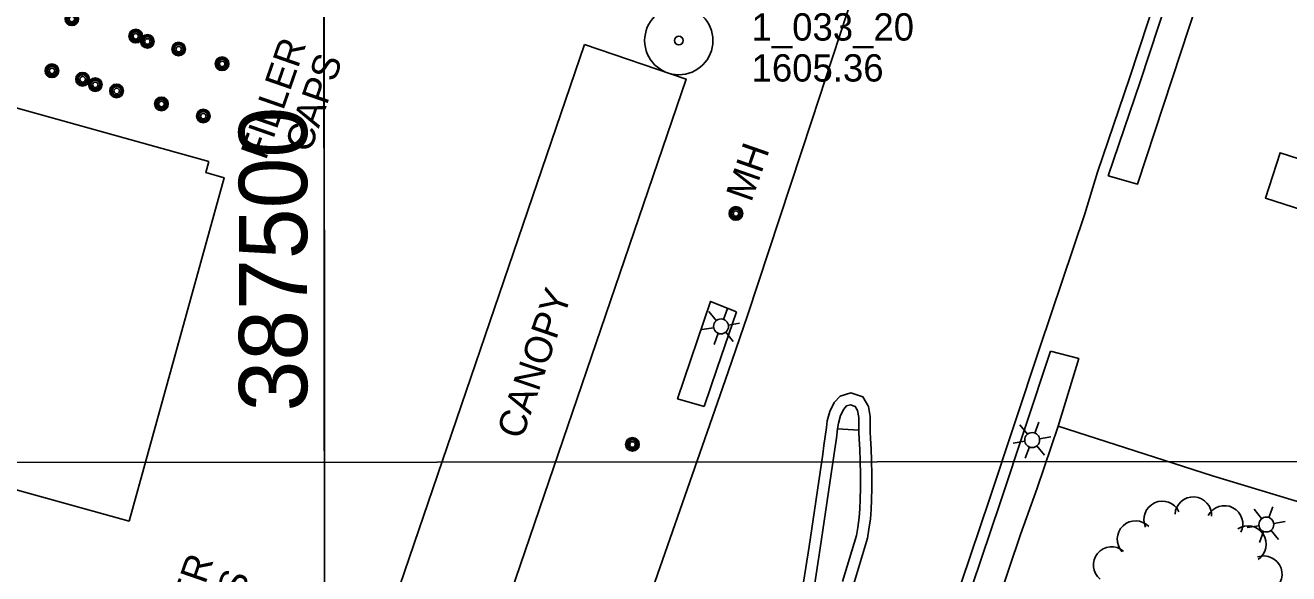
# Model space of a CAD drawing. Extents: x 189384 to 193282, y 256970 to 260388.
# Drawn here: x 190581.3 to 190859, y 258486.9 to 258607.4 of the extents above; entities that cross this region are included whole.
import ezdxf

# ---------------------------------------------------------------- set-up
doc = ezdxf.new("R2010")
doc.units = 0
for name, color, linetype in [('E_BLD_Name', 7, 'Continuous'), ('E_DRN_Grate', 7, 'Continuous'), ('E_DWY', 7, 'Continuous'), ('E_LAND_Vegetation', 7, 'Continuous'), ('E_MAP_GridLines', 7, 'Continuous'), ('E_MAP_PassPoints', 7, 'Continuous'), ('E_MISCPROP', 7, 'Continuous'), ('E_MISCPROP_HvyDash', 7, 'Continuous'), ('E_MISCPROP_HvyLine', 7, 'Continuous'), ('E_PATH_Sidewalk', 7, 'Continuous'), ('E_RDWY', 7, 'Continuous')]:
    doc.layers.add(name, color=color, linetype=linetype)

# ---------------------------------------------------------------- blocks, each defined once
blk = doc.blocks.new('PP_2')
at = {"layer": 'E_MAP_PassPoints'}
for radius in [7.5, 0.96]:
    blk.add_circle((0, 0), radius, dxfattribs=at)
blk = doc.blocks.new('CANOPY')
at = {"layer": 'E_BLD_Name'}
blk.add_text('CANOPY', height=6, rotation=0.0001, dxfattribs=at).set_placement((0, -3.15))
blk = doc.blocks.new('LTP_1')
at = {"layer": 'E_MISCPROP'}
for p, q in [((-0.78, 1.46), (-1.98, 3.76)), ((0.86, 1.37), (2.22, 3.6)), ((-1.61, 0.09), (-4.22, 0.17)), ((1.66, 0), (4.18, -0.07)), ((-0.86, -1.4), (-2.22, -3.59)), ((0.78, -1.44), (2.02, -3.62))]:
    blk.add_line(p, q, dxfattribs=at)
blk.add_circle((0.02, 0.01), 1.64, dxfattribs=at)
blk = doc.blocks.new('MHO_3')
at = {"layer": 'E_DRN_Grate'}
for centre, radius in [((0.04, -0.06), 1.5), ((0.04, -0.06), 1.22), ((0.04, -0.07), 0.968), ((0.01, -0.08), 0.605)]:
    blk.add_circle(centre, radius, dxfattribs=at)
blk = doc.blocks.new('MHO_4')
at = {"layer": 'E_DRN_Grate'}
for centre, radius in [((0.04, -0.06), 1.5), ((0.04, -0.06), 1.22), ((0.04, -0.07), 0.968), ((0.01, -0.08), 0.605)]:
    blk.add_circle(centre, radius, dxfattribs=at)
blk = doc.blocks.new('FILLER')
at = {"layer": 'E_DRN_Grate'}
for s, p in [('FILLER', (-15.52, 1.33)), ('CAPS', (-10.83, -7.33))]:
    blk.add_text(s, height=6, rotation=0, dxfattribs=at).set_placement(p)
blk = doc.blocks.new('LTP_3')
at = {"layer": 'E_MISCPROP'}
for p, q in [((-0.8, 1.43), (-2, 3.73)), ((0.9, 1.42), (2.27, 3.65)), ((-1.64, 0.07), (-4.24, 0.14)), ((-0.88, -1.42), (-2.24, -3.61)), ((0.76, -1.47), (2, -3.65)), ((1.64, -0.02), (4.16, -0.09))]:
    blk.add_line(p, q, dxfattribs=at)
blk.add_circle((0, 0), 1.64, dxfattribs=at)

msp = doc.modelspace()

# ---------------------------------------------------------------- linework, layer by layer
at = {"layer": 'E_DWY'}
for points in [[(190838.59, 258631.76), (190844.7, 258630.27), (190825.76, 258572.54), (190819.3, 258574.37)], [(190737.66, 258544.48), (190731.89, 258546.76), (190724.66, 258525.38), (190730.53, 258523.67)], [(190806.66, 258535.84), (190812.83, 258534.19), (190808.3, 258519.39), (190842.24, 258508.44), (190866.49, 258501.09), (190881.34, 258495.93)]]:
    msp.add_lwpolyline(points, dxfattribs=at)
at = {"layer": 'E_LAND_Vegetation'}
for centre, start, end in [((190831.19, 258498.85), 24.6508, 204.6355), ((190838.01, 258499.79), 356.5943, 176.579), ((190844.88, 258497.87), 332.8143, 152.799), ((190825.32, 258494.53), 43.2202, 223.2049), ((190850.02, 258493.42), 303.8211, 123.8058), ((190820.08, 258488.81), 50.2419, 230.2266), ((190853.5, 258486.82), 289.6424, 109.6271)]:
    msp.add_arc(centre, 4.02, start, end, dxfattribs=at)
at = {"layer": 'E_MAP_GridLines'}
for p, q in [((190647.05, 258511.45), (190646.34, 259511.44)), ((190647.76, 257511.45), (190646.69, 259011.44)), ((189647.05, 258510.74), (191647.04, 258512.16)), ((190147.05, 258511.09), (191647.04, 258512.16)), ((190147.05, 258511.09), (191647.04, 258512.16)), ((190648.11, 257011.45), (190647.05, 258511.45))]:
    msp.add_line(p, q, dxfattribs=at)
at = {"layer": 'E_MISCPROP_HvyDash'}
msp.add_lwpolyline([(190704.19, 258603.25), (190659.43, 258472.12), (190681.81, 258464.48), (190726.56, 258595.62)], close=True, dxfattribs=at)
at = {"layer": 'E_MISCPROP_HvyLine'}
for points in [[(190621.66, 258577.53), (190572.13, 258591.26), (190551.9, 258518.24), (190554.22, 258517.59), (190552.87, 258512.71), (190604.15, 258498.5), (190625.06, 258573.95), (190620.98, 258575.08)], [(190869.17, 258575.55), (190865.95, 258565.58), (190853.86, 258569.48), (190857.08, 258579.45)]]:
    msp.add_lwpolyline(points, close=True, dxfattribs=at)
at = {"layer": 'E_PATH_Sidewalk'}
for points in [[(190808.3, 258519.39), (190803.7, 258505.73), (190800.02, 258495.58), (190787.32, 258457.67), (190784.04, 258448.22), (190777.2, 258428.64), (190779.81, 258418.3), (190783.96, 258403.52), (190793.82, 258400.02), (190807.63, 258395.31)], [(190759.85, 258518.74), (190764.51, 258518.44)]]:
    msp.add_lwpolyline(points, dxfattribs=at)
at = {"layer": 'E_RDWY'}
for points in [[(190773.33, 258737.91), (190774.3, 258740.22), (190780.73, 258737.52), (190783.79, 258735.73), (190787.08, 258733.18), (190788.6, 258731.56), (190792.17, 258726.58), (190794.21, 258721.65), (190795.22, 258716.42), (190795.12, 258712.29), (190794.49, 258708.41), (190792.97, 258704.05), (190787.1, 258685.93), (190774.25, 258647.3), (190766.49, 258624.08), (190754.21, 258586.51)], [(190814.15, 258565.99), (190816.94, 258575.18), (190823.98, 258595.85), (190832.12, 258620.55), (190836.22, 258632.56), (190851.5, 258678.55)], [(190819.3, 258574.37), (190826.35, 258595.05), (190834.49, 258619.76), (190838.59, 258631.76)], [(190740.02, 258543.67), (190754.21, 258586.51)], [(190804.28, 258536.63), (190814.15, 258565.99)], [(190730.53, 258523.67), (190733.4, 258532.08), (190737.66, 258544.48)], [(190732.9, 258522.86), (190735.77, 258531.26), (190740.02, 258543.67)], [(190794.5, 258392.55), (190793.76, 258390.16), (190785.47, 258392.75), (190779.84, 258394.61), (190776.44, 258396.47), (190773.11, 258399), (190770.44, 258401.8), (190768.19, 258405.95), (190765.89, 258412.71), (190765.5, 258417.37), (190765.64, 258421.35), (190766.31, 258424.23), (190769.15, 258432.71), (190776.87, 258454.93), (190793.19, 258503.32), (190804.28, 258536.63)], [(190794.5, 258392.55), (190786.24, 258395.13), (190780.84, 258396.91), (190777.8, 258398.58), (190774.78, 258400.87), (190772.48, 258403.28), (190770.48, 258406.95), (190768.36, 258413.22), (190768.01, 258417.44), (190768.13, 258421.03), (190768.71, 258423.55), (190771.51, 258431.9), (190779.23, 258454.12), (190795.56, 258502.53), (190806.66, 258535.84)], [(190763.32, 258484.52), (190766.44, 258494.77), (190766.73, 258496.72), (190767.05, 258499), (190767.24, 258501.02), (190767.32, 258503.16), (190767.35, 258505.76), (190767.37, 258508.76), (190767.32, 258511.81), (190767.21, 258514.37), (190767.07, 258516.65), (190767.02, 258518.13), (190767, 258519.15), (190766.97, 258521.51), (190766.63, 258523.65), (190765.41, 258525.78), (190762.72, 258526.68), (190760.4, 258525.98), (190759.11, 258524.54), (190758.1, 258522.59), (190757.55, 258520.53), (190757.37, 258519.06), (190757.11, 258517.07), (190756.83, 258515.14), (190756.57, 258513.2), (190753.56, 258492.91), (190751.62, 258480.43)], [(190665.39, 258436.92), (190664.58, 258434.55), (190669.66, 258432.81), (190674.49, 258431.33), (190679.01, 258430.16), (190682.48, 258429.62), (190687.24, 258429.94), (190692.95, 258432.02), (190695.98, 258433.88), (190701.06, 258438.13), (190703.38, 258441.06), (190705.25, 258444.3), (190707.65, 258450.29), (190719.13, 258483.58), (190732.9, 258522.86)], [(190760.93, 258485.25), (190763.99, 258495.32), (190764.26, 258497.08), (190764.56, 258499.29), (190764.74, 258501.18), (190764.82, 258503.22), (190764.85, 258505.79), (190764.87, 258508.74), (190764.82, 258511.73), (190764.71, 258514.23), (190764.57, 258516.53), (190764.52, 258518.07), (190764.5, 258519.12), (190764.48, 258521.29), (190764.24, 258522.8), (190763.72, 258523.71), (190762.68, 258524.06), (190761.79, 258523.79), (190761.18, 258523.11), (190760.45, 258521.68), (190760.01, 258520.05), (190759.85, 258518.74), (190759.58, 258516.73), (190759.31, 258514.8), (190759.05, 258512.85), (190756.03, 258492.54), (190754.09, 258480.01)]]:
    msp.add_lwpolyline(points, dxfattribs=at)

# ---------------------------------------------------------------- block references
at = {"layer": 'E_BLD_Name', "xscale": 0.9999988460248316, "yscale": 0.9999988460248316, "rotation": 71.1549678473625}
msp.add_blockref('CANOPY', (190687.51, 258517.24), dxfattribs=at)
at = {"layer": 'E_DRN_Grate'}
for name, p, rotation in [('MHO_4', (190591.49, 258608.85), 70.86176488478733), ('MHO_4', (190605.53, 258605.05), 70.86176463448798), ('MHO_4', (190608.09, 258603.89), 70.86176458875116), ('MHO_4', (190614.96, 258602.21), 70.8617644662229), ('FILLER', (190640.55, 258591.83), 70.86176400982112), ('MHO_3', (190624.51, 258598.98), 70.86176429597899), ('MHO_4', (190587.12, 258597.44), 70.86176496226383), ('MHO_4', (190593.86, 258595.57), 70.86176484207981), ('MHO_4', (190596.65, 258594.38), 70.86176479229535), ('MHO_4', (190601.33, 258593.01), 70.86176470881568), ('MHO_4', (190611.18, 258590.16), 70.86176453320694), ('MHO_4', (190620.38, 258587.49), 70.86176436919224), ('MHO_3', (190737.42, 258566.09), 70.86176228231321), ('MHO_3', (190714.69, 258515.34), 70.86176268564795), ('FILLER', (190620.21, 258478.46), 70.86176436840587)]:
    msp.add_blockref(name, p, dxfattribs=dict(at, rotation=rotation))
at = {"layer": 'E_MAP_PassPoints', "rotation": -0.00010536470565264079}
msp.add_blockref('PP_2', (190724.94, 258604.08), dxfattribs=at)
at = {"layer": 'E_MISCPROP'}
for name, p, rotation in [('LTP_1', (190734.23, 258541.25), 70.86176233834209), ('LTP_3', (190802.6, 258516.31), 70.86176111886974), ('LTP_3', (190854.06, 258497.74), 70.86176020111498)]:
    msp.add_blockref(name, p, dxfattribs=dict(at, rotation=rotation))

# ---------------------------------------------------------------- texts
at = {"layer": 'E_DRN_Grate'}
msp.add_text('MH', height=6, rotation=70.8619, dxfattribs=at).set_placement((190740.86, 258568.38))
at = {"layer": 'E_MAP_GridLines'}
msp.add_text('  387500  ', height=15, rotation=90.0407, dxfattribs=at).set_placement((190643.3, 258511.44))
at = {"layer": 'E_MAP_PassPoints'}
for s, p in [('1_033_20', (190740.94, 258604.08)), ('1605.36', (190740.94, 258595.08))]:
    msp.add_text(s, height=6, rotation=0, dxfattribs=at).set_placement(p)

doc.saveas('drawing.dxf')
